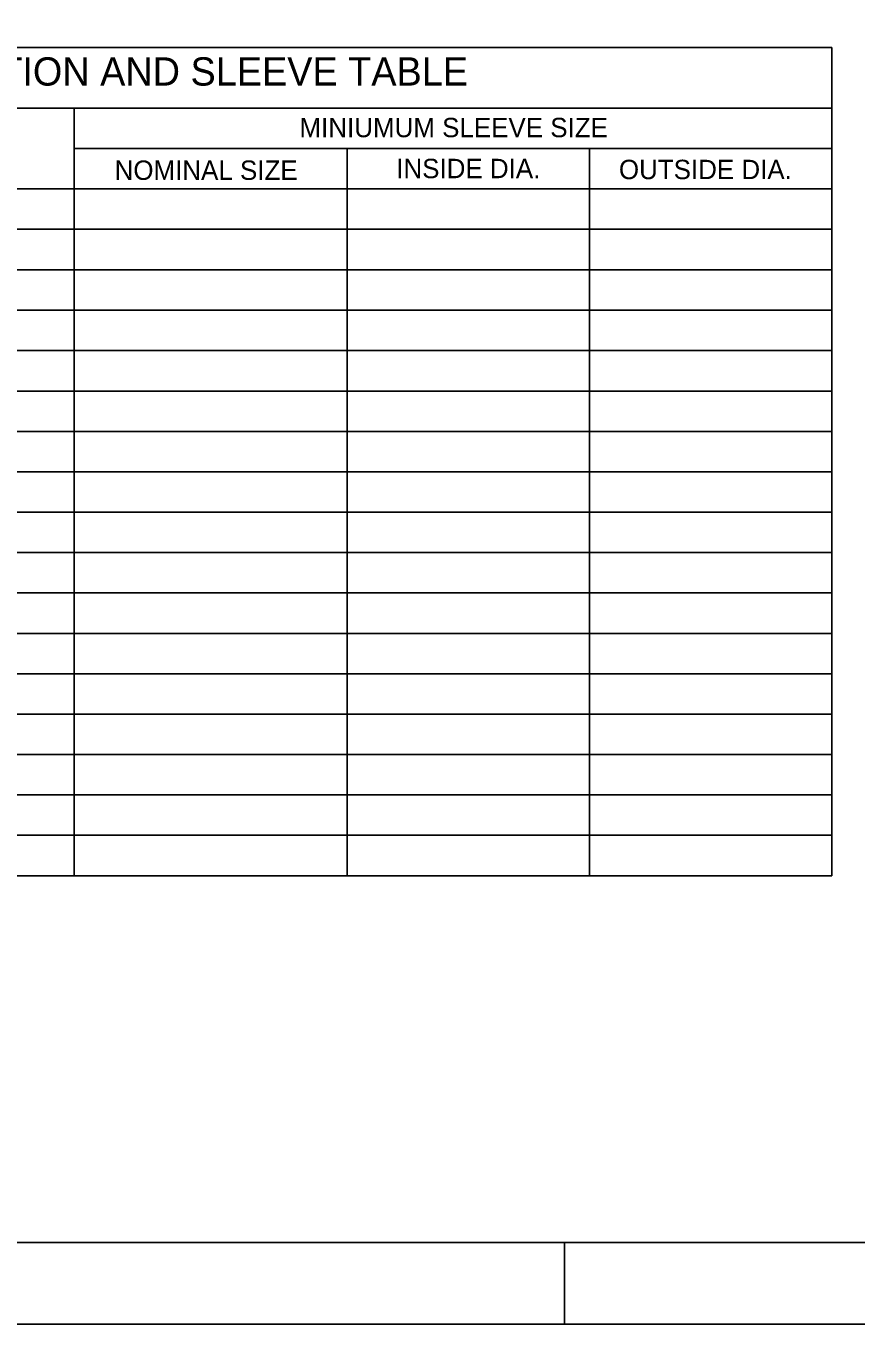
# Model space of a CAD drawing. Extents: x 22422.9 to 22498.9, y 22369.6 to 22415.
# Drawn here: x 22448.26 to 22455.11, y 22369.62 to 22380.33 of the extents above; entities that cross this region are included whole.
import ezdxf

# ---------------------------------------------------------------- set-up
doc = ezdxf.new("R2010")
doc.units = 0
for name, color, linetype in [('Level 1', 7, 'Continuous'), ('Level 10', 7, 'Continuous'), ('Level 2', 7, 'Continuous'), ('Level 4', 7, 'Continuous'), ('Level 7', 7, 'Continuous'), ('Level 9', 7, 'Continuous')]:
    doc.layers.add(name, color=color, linetype=linetype)

msp = doc.modelspace()

# ---------------------------------------------------------------- linework, layer by layer
at = {"layer": 'Level 1'}
msp.add_lwpolyline([(22440.26, 22414.965), (22498.927, 22414.965), (22498.927, 22369.621), (22440.26, 22369.621)], close=True, dxfattribs=at)
at = {"layer": 'Level 10'}
msp.add_line((22452.703, 22369.621), (22452.703, 22370.293), dxfattribs=at)
at = {"layer": 'Level 2'}
for p, q in [((22454.908, 22378.654), (22443.158, 22378.654)), ((22454.908, 22378.32), (22443.158, 22378.32)), ((22454.908, 22377.987), (22443.158, 22377.987)), ((22454.908, 22377.654), (22443.158, 22377.654)), ((22454.908, 22377.32), (22443.158, 22377.32)), ((22454.908, 22376.987), (22443.158, 22376.987)), ((22454.908, 22376.654), (22443.158, 22376.654)), ((22454.908, 22376.32), (22443.158, 22376.32)), ((22454.908, 22375.987), (22443.158, 22375.987)), ((22454.908, 22375.654), (22443.158, 22375.654)), ((22454.908, 22375.32), (22443.158, 22375.32)), ((22454.908, 22374.987), (22443.158, 22374.987)), ((22454.908, 22374.654), (22443.158, 22374.654)), ((22454.908, 22374.32), (22443.158, 22374.32)), ((22454.908, 22373.987), (22443.158, 22373.987)), ((22454.908, 22373.654), (22443.158, 22373.654))]:
    msp.add_line(p, q, dxfattribs=at)
at = {"layer": 'Level 7'}
for p, q in [((22454.908, 22380.154), (22443.158, 22380.154)), ((22454.908, 22373.32), (22454.908, 22380.154)), ((22454.908, 22379.654), (22443.158, 22379.654)), ((22448.658, 22373.32), (22448.658, 22379.654)), ((22454.908, 22379.32), (22448.658, 22379.32)), ((22450.908, 22373.32), (22450.908, 22379.32)), ((22452.908, 22373.32), (22452.908, 22379.32)), ((22454.908, 22378.987), (22443.158, 22378.987)), ((22454.908, 22373.32), (22443.158, 22373.32))]:
    msp.add_line(p, q, dxfattribs=at)
at = {"layer": 'Level 9'}
msp.add_line((22442.26, 22370.293), (22494.591, 22370.293), dxfattribs=at)

# ---------------------------------------------------------------- texts
at = {"layer": 'Level 4'}
for s, height, p in [('PIPE TABULATION AND SLEEVE TABLE', 0.23333, (22446.028, 22379.84)), ('MINIUMUM SLEEVE SIZE', 0.16, (22450.516, 22379.414)), ('NOMINAL SIZE', 0.16, (22448.991, 22379.062)), ('INSIDE DIA.', 0.16, (22451.314, 22379.076)), ('OUTSIDE DIA.', 0.16, (22453.151, 22379.068))]:
    msp.add_text(s, height=height, dxfattribs=at).set_placement(p)

doc.saveas('drawing.dxf')
